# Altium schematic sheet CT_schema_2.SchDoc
size 384 x 228 mm
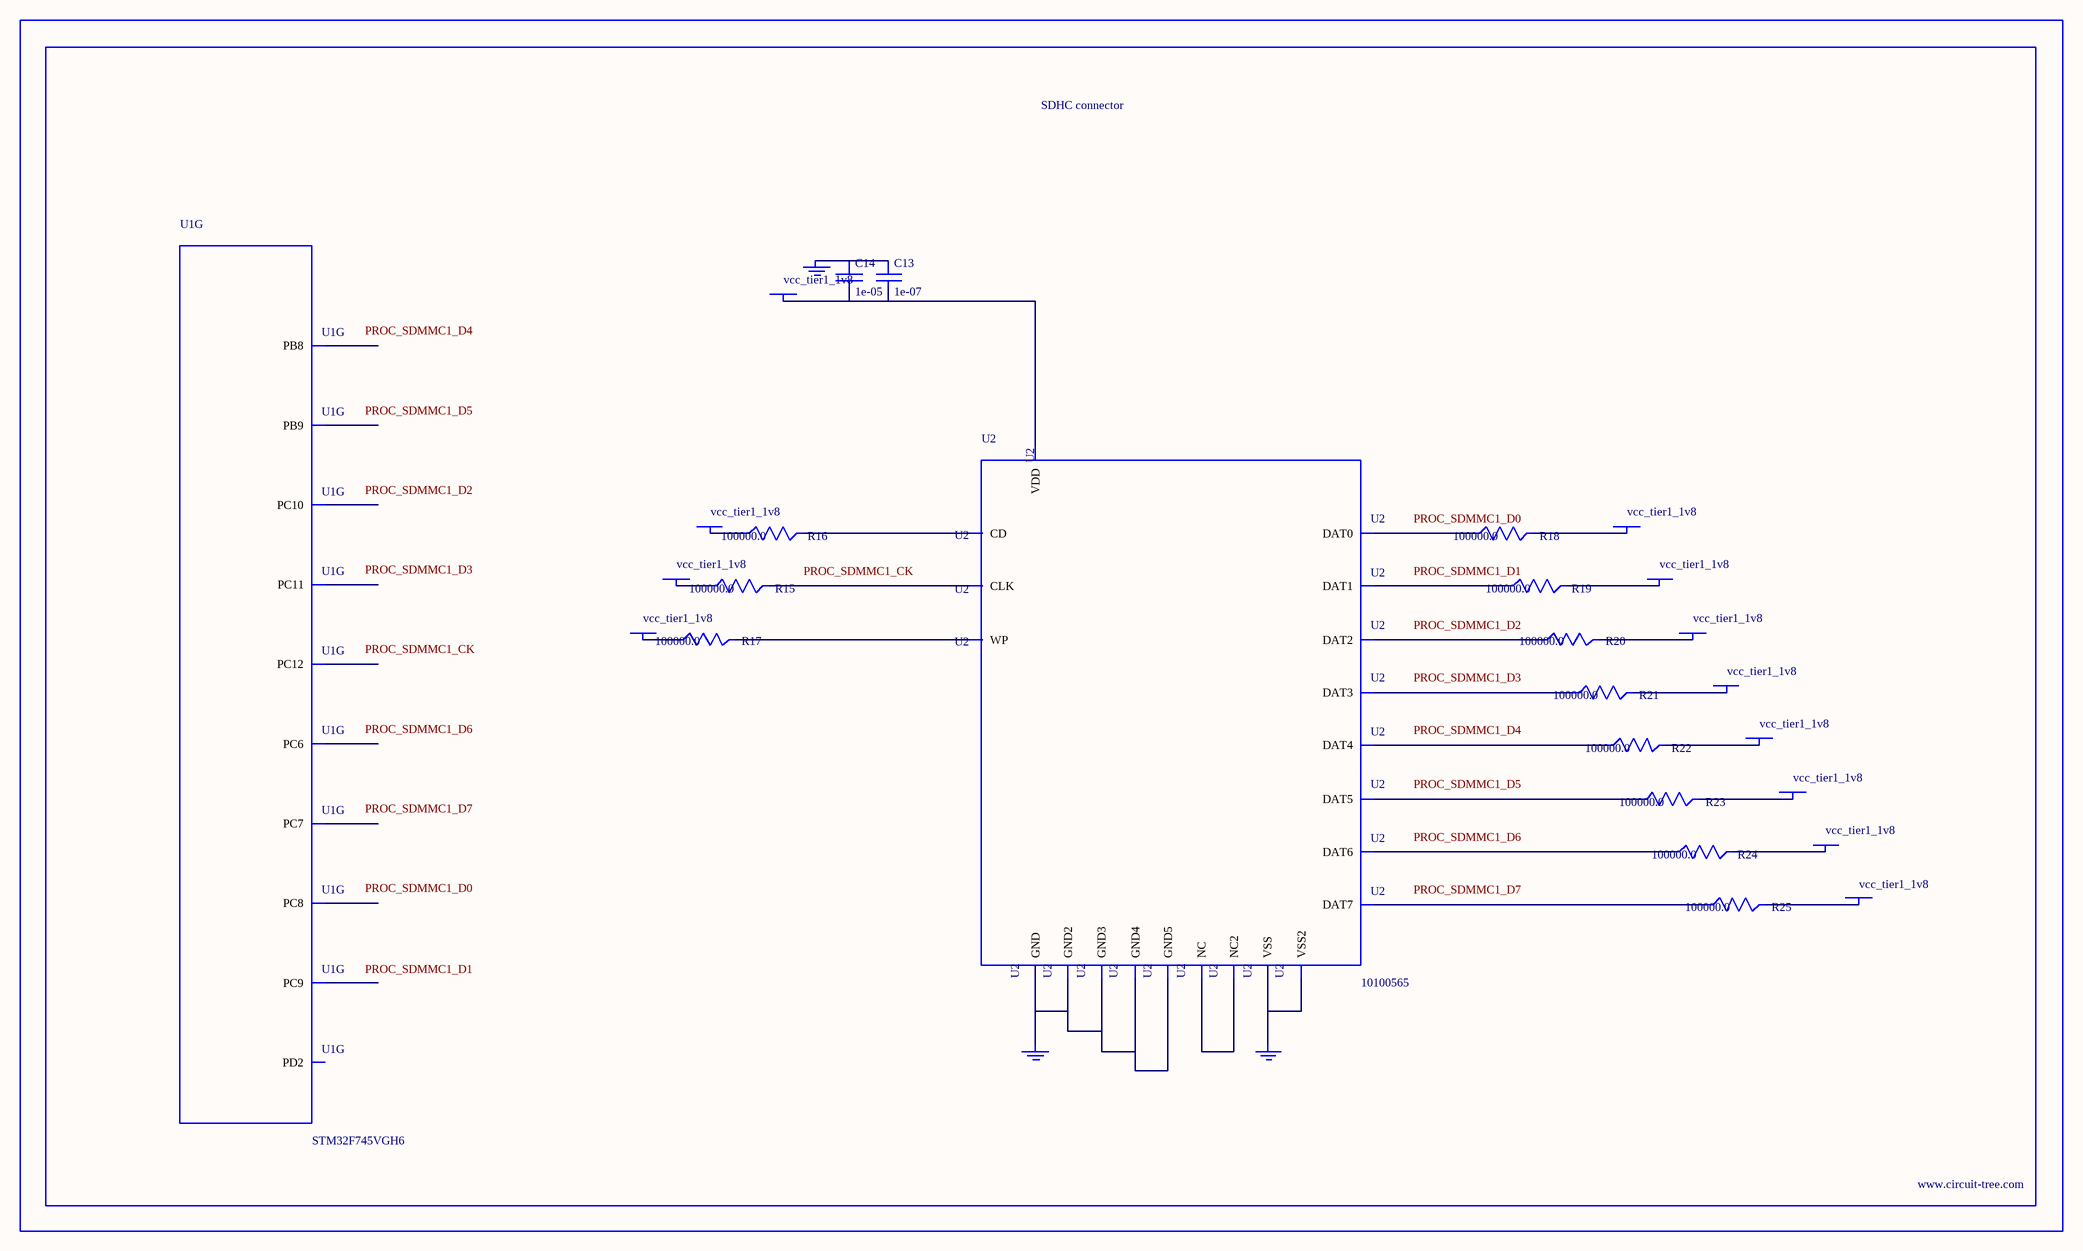
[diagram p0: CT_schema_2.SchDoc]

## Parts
BORDER1  (no value)
C13  1e-07  [C0402]
C14  1e-05  [C0805]
GND_INSTANCE_1_0  (no value)
GND_INSTANCE_1_1  (no value)
GND_INSTANCE_1_2  (no value)
POWER_INSTANCE_1_0  vcc_tier1_1v8
POWER_INSTANCE_1_1  vcc_tier1_1v8
POWER_INSTANCE_1_2  vcc_tier1_1v8
POWER_INSTANCE_1_3  vcc_tier1_1v8
POWER_INSTANCE_1_4  vcc_tier1_1v8
POWER_INSTANCE_1_5  vcc_tier1_1v8
POWER_INSTANCE_1_6  vcc_tier1_1v8
POWER_INSTANCE_1_7  vcc_tier1_1v8
POWER_INSTANCE_1_8  vcc_tier1_1v8
POWER_INSTANCE_1_9  vcc_tier1_1v8
POWER_INSTANCE_1_10  vcc_tier1_1v8
POWER_INSTANCE_1_11  vcc_tier1_1v8
R15  100000.0  [R0603]
R16  100000.0  [R0603]
R17  100000.0  [R0603]
R18  100000.0  [R0603]
R19  100000.0  [R0603]
R20  100000.0  [R0603]
R21  100000.0  [R0603]
R22  100000.0  [R0603]
R23  100000.0  [R0603]
R24  100000.0  [R0603]
R25  100000.0  [R0603]
U1  STM32F745VGH6  [TFBGA100]  (part G of 9)
U2  10100565  [10100565]

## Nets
NetC13_1: C13.1 C14.1 GND_INSTANCE_1_0.0(GND)
NetC13_2: C13.2 C14.2 POWER_INSTANCE_1_7.0(PWR) U2.9(VDD)
NetGND_INSTANCE_1_1_0: GND_INSTANCE_1_1.0(GND) U2.6(VSS) U2.10(VSS2)
NetGND_INSTANCE_1_2_0: GND_INSTANCE_1_2.0(GND) U2.12(GND) U2.16(GND2) U2.17(GND3) U2.20(GND4) U2.21(GND5)
NetPOWER_INSTANCE_1_0_0: POWER_INSTANCE_1_0.0(PWR) R17.1
NetPOWER_INSTANCE_1_1_0: POWER_INSTANCE_1_1.0(PWR) R16.1
NetPOWER_INSTANCE_1_2_0: POWER_INSTANCE_1_2.0(PWR) R19.2
NetPOWER_INSTANCE_1_3_0: POWER_INSTANCE_1_3.0(PWR) R18.2
NetPOWER_INSTANCE_1_4_0: POWER_INSTANCE_1_4.0(PWR) R25.2
NetPOWER_INSTANCE_1_5_0: POWER_INSTANCE_1_5.0(PWR) R24.2
NetPOWER_INSTANCE_1_6_0: POWER_INSTANCE_1_6.0(PWR) R15.1
NetPOWER_INSTANCE_1_8_0: POWER_INSTANCE_1_8.0(PWR) R23.2
NetPOWER_INSTANCE_1_9_0: POWER_INSTANCE_1_9.0(PWR) R22.2
NetPOWER_INSTANCE_1_10_0: POWER_INSTANCE_1_10.0(PWR) R21.2
NetPOWER_INSTANCE_1_11_0: POWER_INSTANCE_1_11.0(PWR) R20.2
NetR15_2: R15.2 U2.8(CLK)
NetR16_2: R16.2 U2.2(CD)
NetR17_2: R17.2 U2.1(WP)
NetR18_1: R18.1 U2.4(DAT0)
NetR19_1: R19.1 U2.3(DAT1)
NetR20_1: R20.1 U2.15(DAT2)
NetR21_1: R21.1 U2.14(DAT3)
NetR22_1: R22.1 U2.13(DAT4)
NetR23_1: R23.1 U2.11(DAT5)
NetR24_1: R24.1 U2.7(DAT6)
NetR25_1: R25.1 U2.5(DAT7)
NetU2_18: U2.18(NC) U2.19(NC2)

Not connected (* = marked no-connect by the designer): U1 A4(PB9) B4(PB8) B7(PD2) B8(PC11) B9(PC10) C8(PC12) E9(PC9) E10(PC7) F9(PC8) F10(PC6)

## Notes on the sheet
- Labels drawn without touching a wire or pin: PROC_SDMMC1_CK, PROC_SDMMC1_D0, PROC_SDMMC1_D1, PROC_SDMMC1_D2, PROC_SDMMC1_D3, PROC_SDMMC1_D4, PROC_SDMMC1_D5, PROC_SDMMC1_D6, PROC_SDMMC1_D7

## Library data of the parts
BORDER1 = BORDER_PAGE1
C13 = C0402C104K3RACTU
C14 = C0805C106K8RACTU
GND_INSTANCE_1_0-GND_INSTANCE_1_2 = GND
POWER_INSTANCE_1_0-POWER_INSTANCE_1_11 = PWR
R15-R25 = RC0603JR-07100KL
